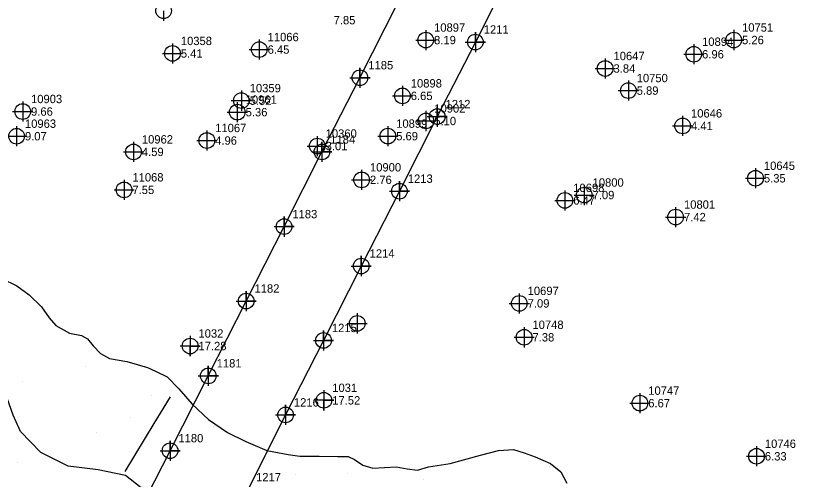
# Model space of a CAD drawing. Extents: x 2062781 to 2066835, y 358981 to 366501.
# Drawn here: x 2064250 to 2064485.4, y 361925.3 to 362063.9 of the extents above; entities that cross this region are included whole.
import ezdxf

# ---------------------------------------------------------------- set-up
doc = ezdxf.new("R2010")
doc.units = 0
for name, color, linetype in [('COGO Default Point Elevation', 7, 'Continuous'), ('COGO Default Point Number', 7, 'Continuous'), ('Exist DTM Breakline Underwater Cogo Elevation', 7, 'Continuous'), ('Exist DTM Breakline Underwater Cogo Number', 7, 'Continuous'), ('Exist DTM Regular Point Underwater CELL', 7, 'Continuous'), ('Exist Structure Major Deck Tunnel Box Culvert', 7, 'Continuous'), ('Exist Structure Major Deck Tunnel Box Culvert Cogo Number', 7, 'Continuous'), ('Exist Structure Major Deck Tunnel Box Culvert Cogo Point CELL', 7, 'Continuous'), ('PH Exist DTM Breakline', 7, 'Continuous'), ('PH Exist DTM Point', 7, 'Continuous')]:
    doc.layers.add(name, color=color, linetype=linetype)

msp = doc.modelspace()

# ---------------------------------------------------------------- linework, layer by layer
at = {"layer": 'Exist DTM Regular Point Underwater CELL'}
for points in [[(2064294.23, 362065.38), (2064294.23, 362062.38)], [(2064372.55, 362059.61), (2064372.55, 362056.61)], [(2064464.6, 362059.63), (2064464.6, 362056.63)], [(2064296.87, 362055.61), (2064296.87, 362052.61)], [(2064322.8, 362056.77), (2064322.8, 362053.77)], [(2064369.55, 362056.61), (2064372.55, 362056.61)], [(2064372.55, 362056.61), (2064375.55, 362056.61)], [(2064372.55, 362056.61), (2064372.55, 362053.61)], [(2064452.65, 362055.37), (2064452.65, 362052.37)], [(2064461.6, 362056.63), (2064464.6, 362056.63)], [(2064464.6, 362056.63), (2064467.6, 362056.63)], [(2064464.6, 362056.63), (2064464.6, 362053.63)], [(2064293.87, 362052.61), (2064296.87, 362052.61)], [(2064296.87, 362052.61), (2064299.87, 362052.61)], [(2064296.87, 362052.61), (2064296.87, 362049.61)], [(2064319.8, 362053.77), (2064322.8, 362053.77)], [(2064322.8, 362053.77), (2064325.8, 362053.77)], [(2064322.8, 362053.77), (2064322.8, 362050.77)], [(2064426.18, 362051.11), (2064426.18, 362048.11)], [(2064449.65, 362052.37), (2064452.65, 362052.37)], [(2064452.65, 362052.37), (2064455.65, 362052.37)], [(2064452.65, 362052.37), (2064452.65, 362049.37)], [(2064423.18, 362048.11), (2064426.18, 362048.11)], [(2064426.18, 362048.11), (2064429.18, 362048.11)], [(2064426.18, 362048.11), (2064426.18, 362045.11)], [(2064433.11, 362044.51), (2064433.11, 362041.51)], [(2064317.45, 362041.5), (2064317.45, 362038.5)], [(2064365.59, 362042.93), (2064365.59, 362039.93)], [(2064430.11, 362041.51), (2064433.11, 362041.51)], [(2064433.11, 362041.51), (2064436.11, 362041.51)], [(2064433.11, 362041.51), (2064433.11, 362038.51)], [(2064314.45, 362038.5), (2064317.45, 362038.5)], [(2064317.45, 362038.5), (2064320.45, 362038.5)], [(2064317.45, 362038.5), (2064317.45, 362035.5)], [(2064362.59, 362039.93), (2064365.59, 362039.93)], [(2064365.59, 362039.93), (2064368.59, 362039.93)], [(2064365.59, 362039.93), (2064365.59, 362036.93)], [(2064252.1, 362038.25), (2064252.1, 362035.25)], [(2064316.24, 362038.06), (2064316.24, 362035.06)], [(2064249.1, 362035.25), (2064252.1, 362035.25)], [(2064252.1, 362035.25), (2064255.1, 362035.25)], [(2064252.1, 362035.25), (2064252.1, 362032.25)], [(2064313.24, 362035.06), (2064316.24, 362035.06)], [(2064316.24, 362035.06), (2064319.24, 362035.06)], [(2064316.24, 362035.06), (2064316.24, 362032.06)], [(2064372.62, 362035.42), (2064372.62, 362032.42)], [(2064449.34, 362033.95), (2064449.34, 362030.95)], [(2064369.62, 362032.42), (2064372.62, 362032.42)], [(2064372.62, 362032.42), (2064375.62, 362032.42)], [(2064372.62, 362032.42), (2064372.62, 362029.42)], [(2064250.28, 362030.87), (2064250.28, 362027.87)], [(2064307.14, 362029.58), (2064307.14, 362026.58)], [(2064361.23, 362030.89), (2064361.23, 362027.89)], [(2064446.34, 362030.95), (2064449.34, 362030.95)], [(2064449.34, 362030.95), (2064452.34, 362030.95)], [(2064449.34, 362030.95), (2064449.34, 362027.95)], [(2064247.28, 362027.87), (2064250.28, 362027.87)], [(2064250.28, 362027.87), (2064253.28, 362027.87)], [(2064250.28, 362027.87), (2064250.28, 362024.87)], [(2064304.14, 362026.58), (2064307.14, 362026.58)], [(2064307.14, 362026.58), (2064310.14, 362026.58)], [(2064307.14, 362026.58), (2064307.14, 362023.58)], [(2064340.15, 362027.92), (2064340.15, 362024.92)], [(2064358.23, 362027.89), (2064361.23, 362027.89)], [(2064361.23, 362027.89), (2064364.23, 362027.89)], [(2064361.23, 362027.89), (2064361.23, 362024.89)], [(2064285.22, 362026.18), (2064285.22, 362023.18)], [(2064337.15, 362024.92), (2064340.15, 362024.92)], [(2064340.15, 362024.92), (2064343.15, 362024.92)], [(2064340.15, 362024.92), (2064340.15, 362021.92)], [(2064282.22, 362023.18), (2064285.22, 362023.18)], [(2064285.22, 362023.18), (2064288.22, 362023.18)], [(2064285.22, 362023.18), (2064285.22, 362020.18)], [(2064353.4, 362017.82), (2064353.4, 362014.82)], [(2064471.12, 362018.29), (2064471.12, 362015.29)], [(2064282.4, 362014.83), (2064282.4, 362011.83)], [(2064350.4, 362014.82), (2064353.4, 362014.82)], [(2064353.4, 362014.82), (2064356.4, 362014.82)], [(2064353.4, 362014.82), (2064353.4, 362011.82)], [(2064468.12, 362015.29), (2064471.12, 362015.29)], [(2064471.12, 362015.29), (2064474.12, 362015.29)], [(2064471.12, 362015.29), (2064471.12, 362012.29)], [(2064419.93, 362013.27), (2064419.93, 362010.27)], [(2064279.4, 362011.83), (2064282.4, 362011.83)], [(2064282.4, 362011.83), (2064285.4, 362011.83)], [(2064282.4, 362011.83), (2064282.4, 362008.83)], [(2064414.15, 362011.68), (2064414.15, 362008.68)], [(2064416.93, 362010.27), (2064419.93, 362010.27)], [(2064419.93, 362010.27), (2064422.93, 362010.27)], [(2064419.93, 362010.27), (2064419.93, 362007.27)], [(2064411.15, 362008.68), (2064414.15, 362008.68)], [(2064414.15, 362008.68), (2064417.15, 362008.68)], [(2064414.15, 362008.68), (2064414.15, 362005.68)], [(2064447.25, 362006.69), (2064447.25, 362003.69)], [(2064444.25, 362003.69), (2064447.25, 362003.69)], [(2064447.25, 362003.69), (2064450.25, 362003.69)], [(2064447.25, 362003.69), (2064447.25, 362000.69)], [(2064400.52, 361980.89), (2064400.52, 361977.89)], [(2064397.52, 361977.89), (2064400.52, 361977.89)], [(2064400.52, 361977.89), (2064403.52, 361977.89)], [(2064400.52, 361977.89), (2064400.52, 361974.89)], [(2064352.09, 361974.92), (2064352.09, 361971.92)], [(2064349.09, 361971.92), (2064352.09, 361971.92)], [(2064352.09, 361971.92), (2064355.09, 361971.92)], [(2064352.09, 361971.92), (2064352.09, 361968.92)], [(2064401.96, 361970.75), (2064401.96, 361967.75)], [(2064302.14, 361968.15), (2064302.14, 361962.15), (2064302.14, 361965.15), (2064305.14, 361965.15), (2064299.14, 361965.15)], [(2064398.96, 361967.75), (2064401.96, 361967.75)], [(2064401.96, 361967.75), (2064404.96, 361967.75)], [(2064401.96, 361967.75), (2064401.96, 361964.75)], [(2064342.12, 361951.91), (2064342.12, 361945.91), (2064342.12, 361948.91), (2064345.12, 361948.91), (2064339.12, 361948.91)], [(2064436.56, 361951.07), (2064436.56, 361948.07)], [(2064433.56, 361948.07), (2064436.56, 361948.07)], [(2064436.56, 361948.07), (2064439.56, 361948.07)], [(2064436.56, 361948.07), (2064436.56, 361945.07)], [(2064471.41, 361935.18), (2064471.41, 361932.18)], [(2064468.41, 361932.18), (2064471.41, 361932.18)], [(2064471.41, 361932.18), (2064474.41, 361932.18)], [(2064471.41, 361932.18), (2064471.41, 361929.18)]]:
    msp.add_lwpolyline(points, dxfattribs=at)
for centre in [(2064294.23, 362065.38), (2064372.55, 362056.61), (2064464.6, 362056.63), (2064296.87, 362052.61), (2064322.8, 362053.77), (2064452.65, 362052.37), (2064426.18, 362048.11), (2064433.11, 362041.51), (2064317.45, 362038.5), (2064365.59, 362039.93), (2064252.1, 362035.25), (2064316.24, 362035.06), (2064372.62, 362032.42), (2064449.34, 362030.95), (2064250.28, 362027.87), (2064307.14, 362026.58), (2064361.23, 362027.89), (2064340.15, 362024.92), (2064285.22, 362023.18), (2064353.4, 362014.82), (2064471.12, 362015.29), (2064282.4, 362011.83), (2064419.93, 362010.27), (2064414.15, 362008.68), (2064447.25, 362003.69), (2064400.52, 361977.89), (2064352.09, 361971.92), (2064401.96, 361967.75), (2064302.14, 361965.15), (2064342.12, 361948.91), (2064436.56, 361948.07), (2064471.41, 361932.18)]:
    msp.add_circle(centre, 2.34, dxfattribs=at)
at = {"layer": 'Exist Structure Major Deck Tunnel Box Culvert'}
for points in [[(2064255.42, 361853.85), (2064275.75, 361893.81), (2064296.14, 361933.85), (2064307.58, 361956.23), (2064318.89, 361978.59), (2064330.21, 362000.83), (2064341.53, 362023.17), (2064352.9, 362045.35), (2064364.2, 362067.75), (2064375.5, 362089.93), (2064386.87, 362112.26), (2064398.19, 362134.56), (2064409.53, 362156.83), (2064420.83, 362179.06), (2064432.19, 362201.49), (2064460.2, 362256.32), (2064487.43, 362309.98), (2064514.61, 362363.36), (2064541.87, 362416.97), (2064569.02, 362470.34), (2064596.26, 362523.95)], [(2064619.37, 362512.07), (2064592.26, 362458.71), (2064565.1, 362405.3), (2064537.77, 362351.7), (2064510.65, 362298.32), (2064483.35, 362244.69), (2064455.33, 362189.72), (2064443.94, 362167.39), (2064432.69, 362145.08), (2064421.28, 362122.77), (2064409.98, 362100.46), (2064398.63, 362078.32), (2064387.39, 362056.02), (2064375.97, 362033.72), (2064364.7, 362011.43), (2064353.29, 361989.06), (2064342.01, 361966.81), (2064330.66, 361944.55), (2064319.35, 361922.18), (2064299.02, 361882.17), (2064278.57, 361842.05)]]:
    msp.add_lwpolyline(points, dxfattribs=at)
at = {"layer": 'Exist Structure Major Deck Tunnel Box Culvert Cogo Point CELL'}
for points in [[(2064384.39, 362056.02), (2064390.39, 362056.02), (2064387.39, 362056.02), (2064387.39, 362059.02), (2064387.39, 362053.02)], [(2064384.39, 362056.02), (2064390.39, 362056.02), (2064387.39, 362056.02), (2064387.39, 362059.02), (2064387.39, 362053.02)], [(2064384.39, 362056.02), (2064390.39, 362056.02), (2064387.39, 362056.02), (2064387.39, 362059.02), (2064387.39, 362053.02)], [(2064349.9, 362045.35), (2064355.9, 362045.35), (2064352.9, 362045.35), (2064352.9, 362048.35), (2064352.9, 362042.35)], [(2064349.9, 362045.35), (2064355.9, 362045.35), (2064352.9, 362045.35), (2064352.9, 362048.35), (2064352.9, 362042.35)], [(2064349.9, 362045.35), (2064355.9, 362045.35), (2064352.9, 362045.35), (2064352.9, 362048.35), (2064352.9, 362042.35)], [(2064372.97, 362033.72), (2064378.97, 362033.72), (2064375.97, 362033.72), (2064375.97, 362036.72), (2064375.97, 362030.72)], [(2064372.97, 362033.72), (2064378.97, 362033.72), (2064375.97, 362033.72), (2064375.97, 362036.72), (2064375.97, 362030.72)], [(2064372.97, 362033.72), (2064378.97, 362033.72), (2064375.97, 362033.72), (2064375.97, 362036.72), (2064375.97, 362030.72)], [(2064338.53, 362023.17), (2064344.53, 362023.17), (2064341.53, 362023.17), (2064341.53, 362026.17), (2064341.53, 362020.17)], [(2064338.53, 362023.17), (2064344.53, 362023.17), (2064341.53, 362023.17), (2064341.53, 362026.17), (2064341.53, 362020.17)], [(2064338.53, 362023.17), (2064344.53, 362023.17), (2064341.53, 362023.17), (2064341.53, 362026.17), (2064341.53, 362020.17)], [(2064361.7, 362011.43), (2064367.7, 362011.43), (2064364.7, 362011.43), (2064364.7, 362014.43), (2064364.7, 362008.43)], [(2064361.7, 362011.43), (2064367.7, 362011.43), (2064364.7, 362011.43), (2064364.7, 362014.43), (2064364.7, 362008.43)], [(2064361.7, 362011.43), (2064367.7, 362011.43), (2064364.7, 362011.43), (2064364.7, 362014.43), (2064364.7, 362008.43)], [(2064327.21, 362000.83), (2064333.21, 362000.83), (2064330.21, 362000.83), (2064330.21, 362003.83), (2064330.21, 361997.83)], [(2064327.21, 362000.83), (2064333.21, 362000.83), (2064330.21, 362000.83), (2064330.21, 362003.83), (2064330.21, 361997.83)], [(2064327.21, 362000.83), (2064333.21, 362000.83), (2064330.21, 362000.83), (2064330.21, 362003.83), (2064330.21, 361997.83)], [(2064350.29, 361989.06), (2064356.29, 361989.06), (2064353.29, 361989.06), (2064353.29, 361992.06), (2064353.29, 361986.06)], [(2064350.29, 361989.06), (2064356.29, 361989.06), (2064353.29, 361989.06), (2064353.29, 361992.06), (2064353.29, 361986.06)], [(2064350.29, 361989.06), (2064356.29, 361989.06), (2064353.29, 361989.06), (2064353.29, 361992.06), (2064353.29, 361986.06)], [(2064315.89, 361978.59), (2064321.89, 361978.59), (2064318.89, 361978.59), (2064318.89, 361981.59), (2064318.89, 361975.59)], [(2064315.89, 361978.59), (2064321.89, 361978.59), (2064318.89, 361978.59), (2064318.89, 361981.59), (2064318.89, 361975.59)], [(2064315.89, 361978.59), (2064321.89, 361978.59), (2064318.89, 361978.59), (2064318.89, 361981.59), (2064318.89, 361975.59)], [(2064339.01, 361966.81), (2064345.01, 361966.81), (2064342.01, 361966.81), (2064342.01, 361969.81), (2064342.01, 361963.81)], [(2064339.01, 361966.81), (2064345.01, 361966.81), (2064342.01, 361966.81), (2064342.01, 361969.81), (2064342.01, 361963.81)], [(2064339.01, 361966.81), (2064345.01, 361966.81), (2064342.01, 361966.81), (2064342.01, 361969.81), (2064342.01, 361963.81)], [(2064304.58, 361956.23), (2064310.58, 361956.23), (2064307.58, 361956.23), (2064307.58, 361959.23), (2064307.58, 361953.23)], [(2064304.58, 361956.23), (2064310.58, 361956.23), (2064307.58, 361956.23), (2064307.58, 361959.23), (2064307.58, 361953.23)], [(2064304.58, 361956.23), (2064310.58, 361956.23), (2064307.58, 361956.23), (2064307.58, 361959.23), (2064307.58, 361953.23)], [(2064327.66, 361944.55), (2064333.66, 361944.55), (2064330.66, 361944.55), (2064330.66, 361947.55), (2064330.66, 361941.55)], [(2064327.66, 361944.55), (2064333.66, 361944.55), (2064330.66, 361944.55), (2064330.66, 361947.55), (2064330.66, 361941.55)], [(2064327.66, 361944.55), (2064333.66, 361944.55), (2064330.66, 361944.55), (2064330.66, 361947.55), (2064330.66, 361941.55)], [(2064293.14, 361933.85), (2064299.14, 361933.85), (2064296.14, 361933.85), (2064296.14, 361936.85), (2064296.14, 361930.85)], [(2064293.14, 361933.85), (2064299.14, 361933.85), (2064296.14, 361933.85), (2064296.14, 361936.85), (2064296.14, 361930.85)], [(2064293.14, 361933.85), (2064299.14, 361933.85), (2064296.14, 361933.85), (2064296.14, 361936.85), (2064296.14, 361930.85)]]:
    msp.add_lwpolyline(points, dxfattribs=at)
for centre in [(2064387.39, 362056.02), (2064387.39, 362056.02), (2064387.39, 362056.02), (2064352.9, 362045.35), (2064352.9, 362045.35), (2064352.9, 362045.35), (2064375.97, 362033.72), (2064375.97, 362033.72), (2064375.97, 362033.72), (2064341.53, 362023.17), (2064341.53, 362023.17), (2064341.53, 362023.17), (2064364.7, 362011.43), (2064364.7, 362011.43), (2064364.7, 362011.43), (2064330.21, 362000.83), (2064330.21, 362000.83), (2064330.21, 362000.83), (2064353.29, 361989.06), (2064353.29, 361989.06), (2064353.29, 361989.06), (2064318.89, 361978.59), (2064318.89, 361978.59), (2064318.89, 361978.59), (2064342.01, 361966.81), (2064342.01, 361966.81), (2064342.01, 361966.81), (2064307.58, 361956.23), (2064307.58, 361956.23), (2064307.58, 361956.23), (2064330.66, 361944.55), (2064330.66, 361944.55), (2064330.66, 361944.55), (2064296.14, 361933.85), (2064296.14, 361933.85), (2064296.14, 361933.85)]:
    msp.add_circle(centre, 2.34, dxfattribs=at)
at = {"layer": 'PH Exist DTM Breakline'}
for points in [[(2064245.83, 361985.31), (2064250.31, 361983.14), (2064254.02, 361980.45), (2064257.74, 361976.91), (2064260, 361973.58), (2064261.96, 361971.28), (2064266.12, 361969.01), (2064269.69, 361968.3), (2064271.5, 361967.26), (2064273.18, 361965.18), (2064275.35, 361962.91), (2064278.09, 361961.4), (2064283.22, 361960.49), (2064289.43, 361958.7), (2064291.81, 361957.62), (2064295.3, 361955.91), (2064298.75, 361952.3), (2064302.74, 361947.8), (2064307.63, 361943.21), (2064313.32, 361939.3), (2064318.76, 361936.59), (2064325.06, 361933.96), (2064331.41, 361932.72), (2064334.97, 361932.24), (2064340.74, 361932.24), (2064346.28, 361932.15), (2064349.33, 361932.08), (2064351.25, 361931.19), (2064353.76, 361929.52), (2064356.74, 361928.59), (2064360.19, 361928.82), (2064363.72, 361929.07), (2064366.97, 361928.42), (2064370.14, 361928.08), (2064373.42, 361929.01), (2064379.87, 361930.06), (2064388.89, 361932.53), (2064394.28, 361933.94), (2064398.81, 361934.24), (2064402.01, 361933.23), (2064405.29, 361932.04), (2064409.85, 361930.03), (2064412.9, 361927.58), (2064414.72, 361924.17)], [(2064347.08, 361899.76), (2064335.27, 361906.48), (2064323.58, 361907.86), (2064312.7, 361908.49), (2064297.61, 361916.01), (2064287.51, 361922.76), (2064282.79, 361926.44), (2064274.67, 361928.18), (2064265.74, 361929.27), (2064257.51, 361933.27), (2064251.47, 361939.6), (2064249.24, 361944.52), (2064247.44, 361949.52), (2064245.07, 361952.31), (2064238.5, 361956.15), (2064230.65, 361959.03), (2064225.83, 361962), (2064221.37, 361966.68)], [(2064282.71, 361927.6), (2064291.44, 361941.94), (2064296.31, 361949.92)]]:
    msp.add_lwpolyline(points, dxfattribs=at)
at = {"layer": 'PH Exist DTM Point'}
for p, q in [((2064270.87, 361959.13), (2064270.87, 361959.13)), ((2064252.17, 361954.41), (2064252.17, 361954.41)), ((2064290.65, 361950.27), (2064290.65, 361950.27)), ((2064284.29, 361943.78), (2064284.29, 361943.78)), ((2064274.16, 361939.38), (2064274.16, 361939.38)), ((2064250.63, 361930.24), (2064250.63, 361930.24)), ((2064333.69, 361926.65), (2064333.69, 361926.65)), ((2064349.19, 361927.13), (2064349.19, 361927.13)), ((2064371.91, 361925.37), (2064371.91, 361925.37))]:
    msp.add_line(p, q, dxfattribs=at)

# ---------------------------------------------------------------- texts
at = {"layer": 'COGO Default Point Elevation'}
for s, p in [('7.85', (2064345.03, 362061.31)), ('8.19', (2064375.05, 362055.36)), ('5.26', (2064467.1, 362055.38)), ('6.45', (2064325.3, 362052.52)), ('5.41', (2064299.37, 362051.36)), ('6.96', (2064455.15, 362051.12)), ('3.84', (2064428.68, 362046.86)), ('6.65', (2064368.09, 362038.68)), ('5.89', (2064435.61, 362040.26)), ('5.52', (2064319.95, 362037.25)), ('9.66', (2064254.6, 362034)), ('5.36', (2064318.74, 362033.81)), ('5.10', (2064375.12, 362031.17)), ('4.41', (2064451.84, 362029.7)), ('9.07', (2064252.78, 362026.62)), ('5.69', (2064363.73, 362026.64)), ('4.96', (2064309.64, 362025.33)), ('4.59', (2064287.72, 362021.93)), ('3.01', (2064342.65, 362023.67)), ('2.76', (2064355.9, 362013.57)), ('5.35', (2064473.62, 362014.04)), ('7.55', (2064284.9, 362010.58)), ('7.09', (2064422.43, 362009.03)), ('6.47', (2064416.65, 362007.43)), ('7.42', (2064449.75, 362002.44)), ('7.09', (2064403.02, 361976.64)), ('7.38', (2064404.46, 361966.5)), ('6.67', (2064439.06, 361946.82)), ('6.33', (2064473.91, 361930.93))]:
    msp.add_text(s, height=2.5, dxfattribs=at).set_placement(p)
at = {"layer": 'COGO Default Point Number'}
for s, p in [('10897', (2064375.05, 362059.11)), ('10751', (2064467.1, 362059.13)), ('10358', (2064299.37, 362055.11)), ('11066', (2064325.3, 362056.27)), ('10894', (2064455.15, 362054.87)), ('10647', (2064428.68, 362050.61)), ('10750', (2064435.61, 362044.01)), ('10359', (2064319.95, 362041)), ('10898', (2064368.09, 362042.43)), ('10903', (2064254.6, 362037.75)), ('10961', (2064318.74, 362037.56)), ('10902', (2064375.12, 362034.92)), ('10646', (2064451.84, 362033.45)), ('10963', (2064252.78, 362030.37)), ('11067', (2064309.64, 362029.08)), ('10899', (2064363.73, 362030.39)), ('10360', (2064342.65, 362027.42)), ('10962', (2064287.72, 362025.68)), ('10900', (2064355.9, 362017.32)), ('10645', (2064473.62, 362017.79)), ('11068', (2064284.9, 362014.33)), ('10800', (2064422.43, 362012.78)), ('10698', (2064416.65, 362011.18)), ('10801', (2064449.75, 362006.19)), ('10697', (2064403.02, 361980.39)), ('10748', (2064404.46, 361970.25)), ('10747', (2064439.06, 361950.57)), ('10746', (2064473.91, 361934.68))]:
    msp.add_text(s, height=2.5, dxfattribs=at).set_placement(p)
at = {"layer": 'Exist DTM Breakline Underwater Cogo Elevation'}
for s, p in [('17.28', (2064304.64, 361963.9)), ('17.52', (2064344.62, 361947.66))]:
    msp.add_text(s, height=2.5, dxfattribs=at).set_placement(p)
at = {"layer": 'Exist DTM Breakline Underwater Cogo Number'}
for s, p in [('1032', (2064304.64, 361967.65)), ('1031', (2064344.62, 361951.41))]:
    msp.add_text(s, height=2.5, dxfattribs=at).set_placement(p)
at = {"layer": 'Exist Structure Major Deck Tunnel Box Culvert Cogo Number'}
for s, p in [('1211', (2064389.89, 362058.52)), ('1211', (2064389.89, 362058.52)), ('1211', (2064389.89, 362058.52)), ('1185', (2064355.4, 362047.85)), ('1185', (2064355.4, 362047.85)), ('1185', (2064355.4, 362047.85)), ('1212', (2064378.47, 362036.22)), ('1212', (2064378.47, 362036.22)), ('1212', (2064378.47, 362036.22)), ('1184', (2064344.03, 362025.67)), ('1184', (2064344.03, 362025.67)), ('1184', (2064344.03, 362025.67)), ('1213', (2064367.2, 362013.93)), ('1213', (2064367.2, 362013.93)), ('1213', (2064367.2, 362013.93)), ('1183', (2064332.71, 362003.33)), ('1183', (2064332.71, 362003.33)), ('1183', (2064332.71, 362003.33)), ('1214', (2064355.79, 361991.56)), ('1214', (2064355.79, 361991.56)), ('1214', (2064355.79, 361991.56)), ('1182', (2064321.39, 361981.09)), ('1182', (2064321.39, 361981.09)), ('1182', (2064321.39, 361981.09)), ('1215', (2064344.51, 361969.31)), ('1215', (2064344.51, 361969.31)), ('1215', (2064344.51, 361969.31)), ('1181', (2064310.08, 361958.73)), ('1181', (2064310.08, 361958.73)), ('1181', (2064310.08, 361958.73)), ('1216', (2064333.16, 361947.05)), ('1216', (2064333.16, 361947.05)), ('1216', (2064333.16, 361947.05)), ('1180', (2064298.64, 361936.35)), ('1180', (2064298.64, 361936.35)), ('1180', (2064298.64, 361936.35)), ('1217', (2064321.85, 361924.68)), ('1217', (2064321.85, 361924.68)), ('1217', (2064321.85, 361924.68))]:
    msp.add_text(s, height=2.5, dxfattribs=at).set_placement(p)

doc.saveas('drawing.dxf')
